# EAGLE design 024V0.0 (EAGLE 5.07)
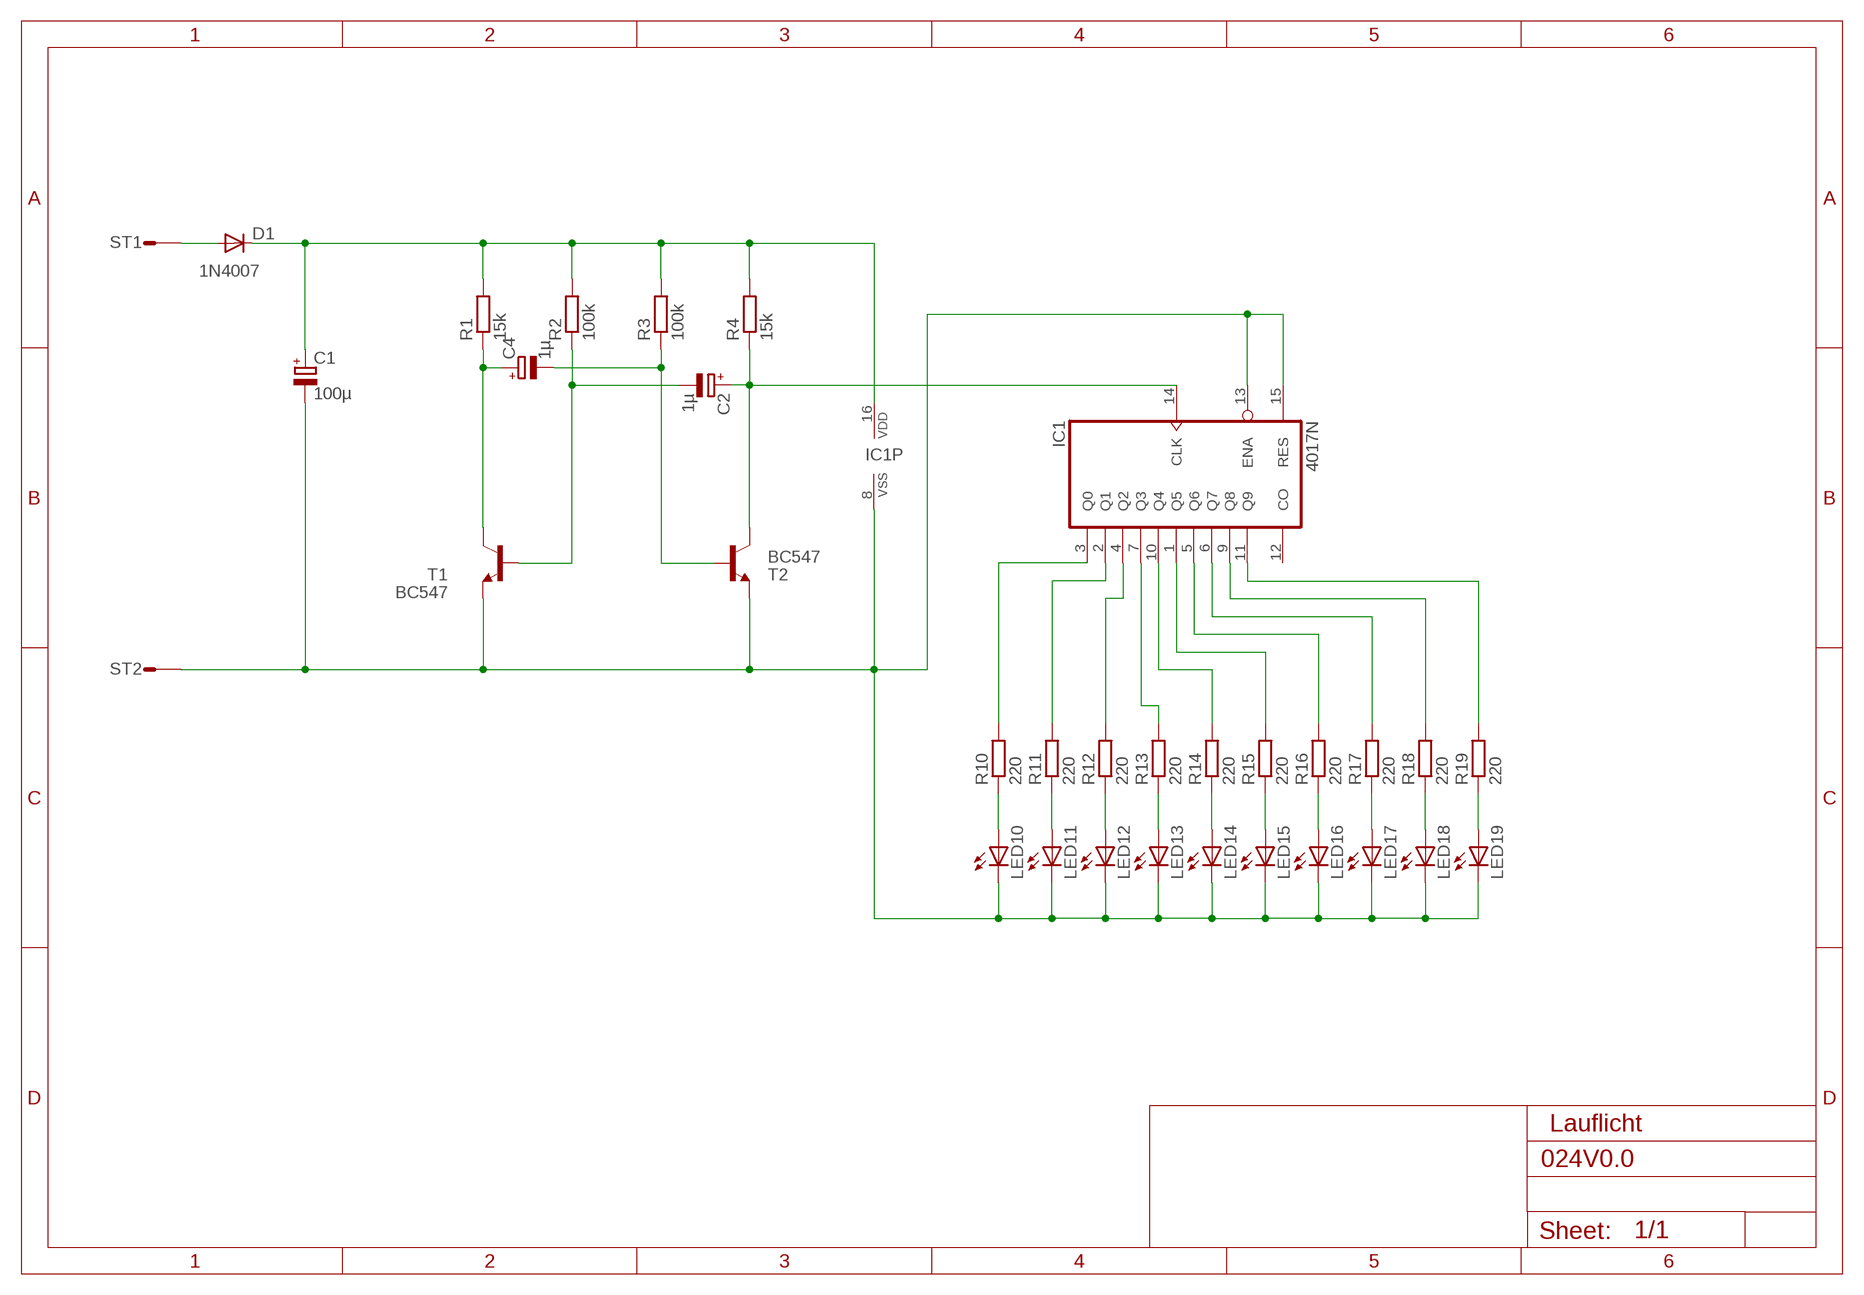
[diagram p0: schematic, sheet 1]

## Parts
C1  100µ  CPOL-EUE5-10.5  [E5-10,5]
C2  1µ  CPOL-EUE2.5-5  [E2,5-5]
C4  1µ  CPOL-EUE2.5-5  [E2,5-5]
D1  1N4007  1N4004  [DO41-10]
IC1  4017N  [DIL16]
LED10  LED3MM  [LED3MM]
LED11  LED3MM  [LED3MM]
LED12  LED3MM  [LED3MM]
LED13  LED3MM  [LED3MM]
LED14  LED3MM  [LED3MM]
LED15  LED3MM  [LED3MM]
LED16  LED3MM  [LED3MM]
LED17  LED3MM  [LED3MM]
LED18  LED3MM  [LED3MM]
LED19  LED3MM  [LED3MM]
R1  15k  R-EU_0207/10  [0207/10]
R2  100k  R-EU_0207/10  [0207/10]
R3  100k  R-EU_0207/10  [0207/10]
R4  15k  R-EU_0207/10  [0207/10]
R10  220  R-EU_0207/10  [0207/10]
R11  220  R-EU_0207/10  [0207/10]
R12  220  R-EU_0207/10  [0207/10]
R13  220  R-EU_0207/10  [0207/10]
R14  220  R-EU_0207/10  [0207/10]
R15  220  R-EU_0207/10  [0207/10]
R16  220  R-EU_0207/10  [0207/10]
R17  220  R-EU_0207/10  [0207/10]
R18  220  R-EU_0207/10  [0207/10]
R19  220  R-EU_0207/10  [0207/10]
ST1  ST2,8  [ST2,8]
ST2  ST2,8  [ST2,8]
T1  BC547  [TO92-5]
T2  BC547  [TO92-5]

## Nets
GND: C1.- IC1.8(VSS) IC1.13(ENA) IC1.15(RES) LED10.K(C) LED11.K(C) LED12.K(C) LED13.K(C) LED14.K(C) LED15.K(C) LED16.K(C) LED17.K(C) LED18.K(C) LED19.K(C) ST2.1(ST) T1.1(E) T2.1(E)
N$1: D1.A ST1.1(ST)
N$2: C1.+ D1.C IC1.16(VDD) R1.2 R2.2 R3.2 R4.2
N$4: C4.+ R1.1 T1.3(C)
N$5: C4.- R3.1 T2.2(B)
N$6: C2.+ IC1.14(CLK) R4.1 T2.3(C)
N$7: C2.- R2.1 T1.2(B)
N$8: LED10.A R10.1
N$9: LED11.A R11.1
N$10: LED12.A R12.1
N$11: LED13.A R13.1
N$12: LED14.A R14.1
N$13: LED15.A R15.1
N$14: LED16.A R16.1
N$15: LED17.A R17.1
N$16: LED18.A R18.1
N$17: LED19.A R19.1
N$18: IC1.3(Q0) R10.2
N$19: IC1.2(Q1) R11.2
N$20: IC1.4(Q2) R12.2
N$21: IC1.11(Q9) R19.2
N$22: IC1.9(Q8) R18.2
N$23: IC1.6(Q7) R17.2
N$24: IC1.5(Q6) R16.2
N$25: IC1.1(Q5) R15.2
N$26: IC1.10(Q4) R14.2
N$27: IC1.7(Q3) R13.2
Unconnected: IC1.12(CO)

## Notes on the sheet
- Lauflicht

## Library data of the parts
C1 = resistor:CPOL-EU: POLARIZED CAPACITOR, European symbol
C2 C4 = rcl:CPOL-EU: POLARIZED CAPACITOR, European symbol
D1 = diode:1N4004: DIODE
IC1 = 40xx:4017: COUNTER/DIVIDER
LED10-LED19 = led:LED: LED
R1-R4 R10-R19 = armin:R-EU_: RESISTOR, European symbol
ST1 ST2 = con-rib:ST2,8: RIBBON CABLE CONNECTOR
T1 T2 = armin:BC547: NPN TRANSISTOR

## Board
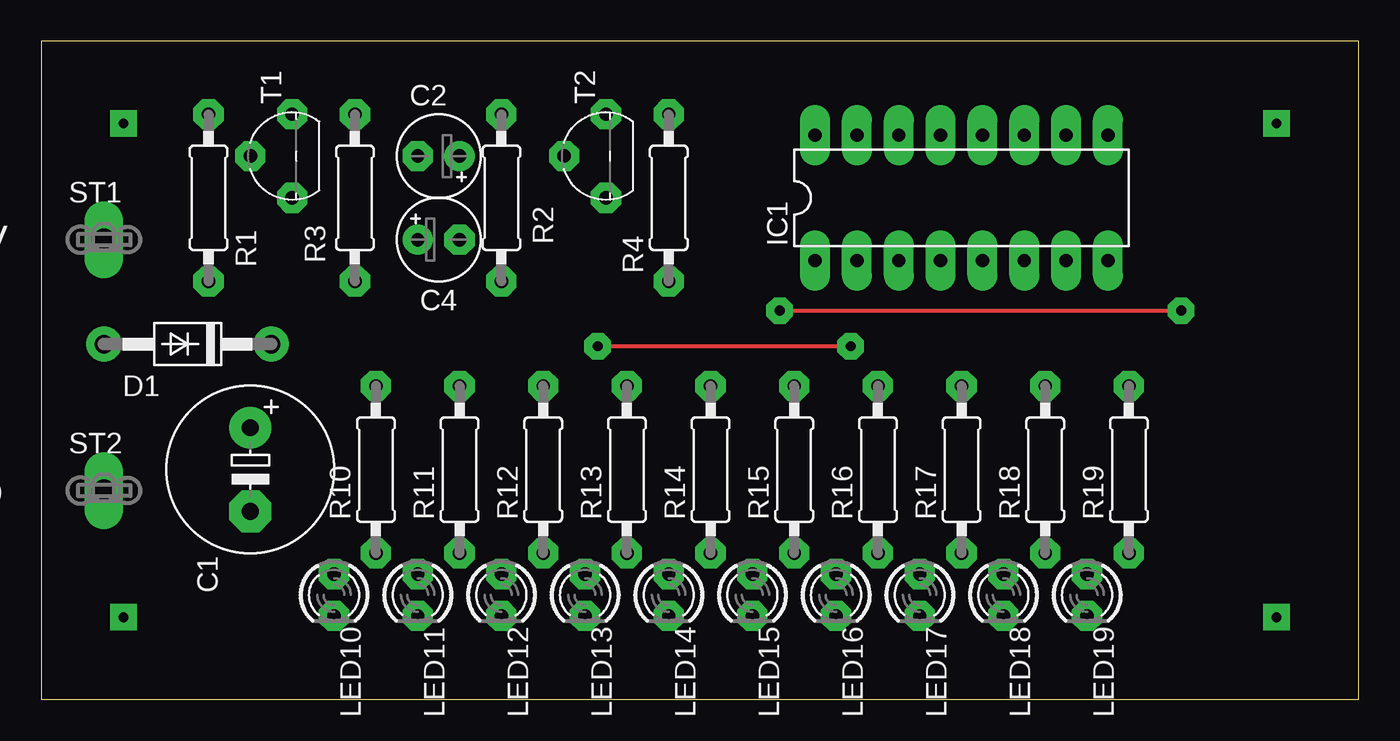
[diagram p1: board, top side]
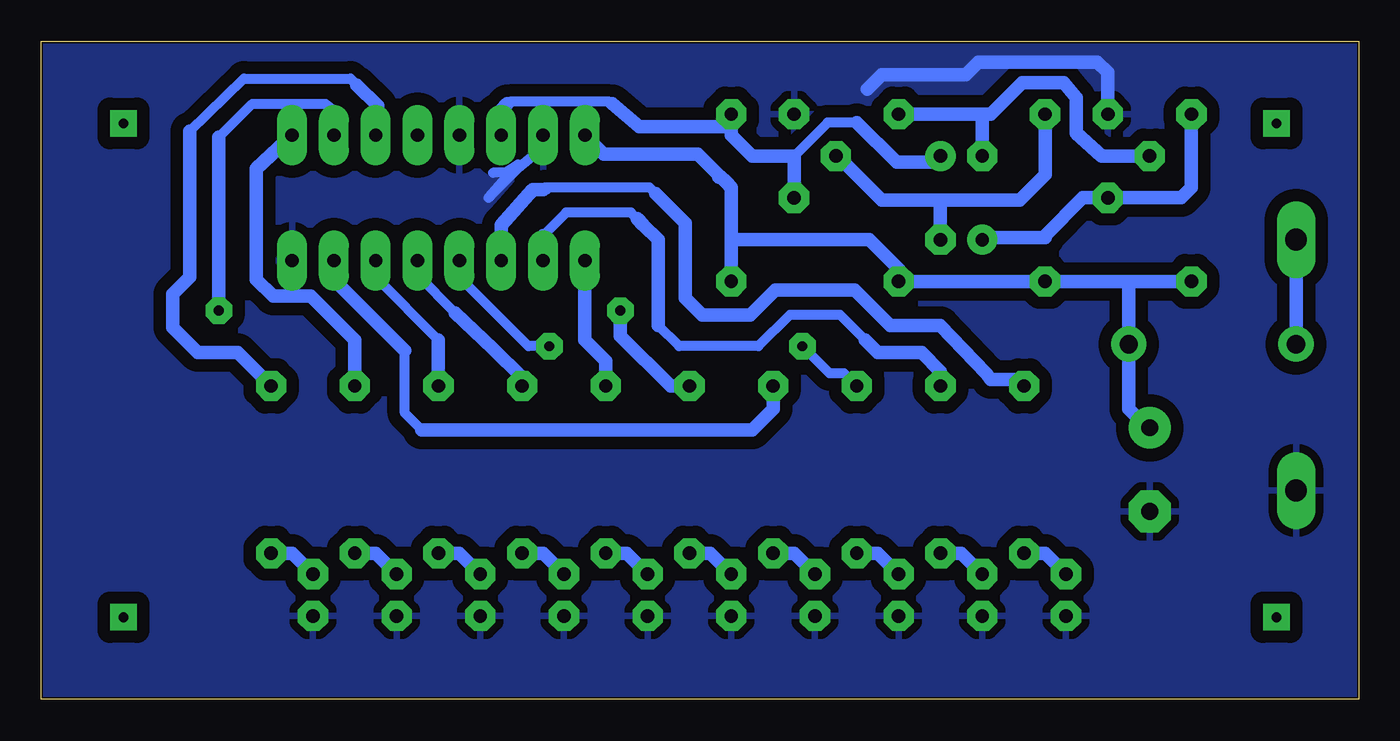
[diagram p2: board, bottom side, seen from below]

Size 80 x 40 mm. Coordinates in mm from the lower left corner, seen from the top.
Outline: 0,0 80,0 80,40 0,40 0,0
Copper layers (1*16): Top 0.035mm / dielectric 1.5mm / Bottom 0.035mm
Design rules "default *": minimum track width 10mil, minimum drill 24mil, track to track 30mil, track to pad 30mil, pad to pad 25mil, via to via 8mil, smd to smd 8mil, copper to edge 5mil, drill to drill 8mil, minimum pad ring 20mil, minimum via ring 20mil, stop-mask expansion 4mil, vias tented up to drill 0mil, thermal gap 20mil
bKeepout: 2 lines
bRestrict: 2 lines

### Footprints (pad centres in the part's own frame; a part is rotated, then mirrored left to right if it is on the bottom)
E5-10,5 = drill 1.016 pad 2.54 round: + -2.54,0 | drill 1.016 pad 2.54 octagon: - 2.54,0
E2,5-5 = drill 0.813 pad 1.6 round: + -1.27,0 | drill 0.813 pad 1.6 octagon: - 1.27,0
DO41-10 = drill 1.118 round: A 5.08,0; C -5.08,0
DIL16 = drill 0.813 long: 1 -8.89,-3.81; 2 -6.35,-3.81; 3 -3.81,-3.81; 4 -1.27,-3.81; 5 1.27,-3.81; 6 3.81,-3.81; 7 6.35,-3.81; 8 8.89,-3.81; 9 8.89,3.81; 10 6.35,3.81; 11 3.81,3.81; 12 1.27,3.81; 13 -1.27,3.81; 14 -3.81,3.81; 15 -6.35,3.81; 16 -8.89,3.81
LED3MM = drill 0.813 octagon: A -1.27,0; K 1.27,0
0207/10 = drill 0.813 octagon: 1 -5.08,0; 2 5.08,0
ST2,8 = drill 1.321 long: 1 0,0
TO92-5 = drill 0.813 octagon: 1 2.54,0; 2 0,2.54; 3 -2.54,0

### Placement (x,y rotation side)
C1  12.7,13.97 270 top
C2  24.13,33.02 180 top
C4  24.13,27.94 0 top
D1  8.89,21.59 180 top
IC1  55.88,30.48 0 top
LED10  17.78,6.35 270 top
LED11  22.86,6.35 270 top
LED12  27.94,6.35 270 top
LED13  33.02,6.35 270 top
LED14  38.1,6.35 270 top
LED15  43.18,6.35 270 top
LED16  48.26,6.35 270 top
LED17  53.34,6.35 270 top
LED18  58.42,6.35 270 top
LED19  63.5,6.35 270 top
R1  10.16,30.48 270 top
R2  27.94,30.48 270 top
R3  19.05,30.48 270 top
R4  38.1,30.48 270 top
R10  20.32,13.97 90 top
R11  25.4,13.97 90 top
R12  30.48,13.97 90 top
R13  35.56,13.97 90 top
R14  40.64,13.97 90 top
R15  45.72,13.97 90 top
R16  50.8,13.97 90 top
R17  55.88,13.97 90 top
R18  60.96,13.97 90 top
R19  66.04,13.97 90 top
ST1  3.81,27.94 0 top
ST2  3.81,12.7 0 top
T1  15.24,33.02 90 top
T2  34.29,33.02 90 top

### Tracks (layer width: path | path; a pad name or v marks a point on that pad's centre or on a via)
GND
  Bottom 0.61: IC1.15 49.53,33.53 51.05,32.26 52.83,30.48 51.05,32.51 51.82,32 52.58,32
  Bottom 0.813: T1.1 15.24,38.1 15.88,38.73 23.11,38.73 23.88,37.97 28.96,37.97 29.84,37.08
  pour Bottom: 0,0 0,40.64 80.01,40.64 80.01,0
  pour Bottom: 60.07,12.45 72.01,12.45 72.01,15.88 60.07,15.88
  pour Bottom: 1.52,7.87 7.11,7.87 7.11,10.41 1.52,10.41
  pour Bottom: 7.87,21.34 7.87,31.37 5.84,31.37 5.84,21.34
N$1
  Bottom 0.813: D1.A ST1.1
N$2
  Bottom 0.813: C1.+ 12.83,16.51 13.97,17.65 D1.C 13.97,25.27 14.1,25.4 | 38.8,31.81 38.42,31.43 38.1,31.11 38.1,28.07 | 38.1,28.07 R4.2 | 38.1,28.07 37.97,27.94 29.72,27.94 27.94,26.16 R2.2 R3.2 14.1,25.4 | 38.8,31.81 38.86,31.75 | IC1.16 45.85,33.15 40.13,33.15 38.8,31.81 | 14.1,25.4 R1.2
N$4
  Bottom 0.813: C4.+ 22.73,28.07 19.05,28.07 19.05,28.19 16.76,30.48 T1.3 10.79,30.48 10.16,31.11 R1.1
N$5
  Bottom 0.813: 25.4,28.32 C4.- 25.4,30.35 | R3.1 19.05,31.88 20.57,30.35 25.4,30.35 | T2.2 31.62,33.02 28.96,30.35 25.4,30.35
N$6
  Bottom 0.61: 30.48,35.05 32.26,35.05 34.29,33.02 | 45.34,36.2 45.47,36.2 45.47,36.32 51.56,36.32 51.56,36.2 51.69,36.2
  Bottom 0.813: C2.+ 25.78,32.64 28.07,32.64 30.48,35.05 | 34.29,33.02 34.29,32.89 | 34.29,32.89 T2.3 | 38.1,34.8 38.1,34.29 36.83,33.02 34.42,33.02 34.29,32.89 | IC1.14 52.07,35.81 51.69,36.2 | 45.34,36.2 43.69,34.8 38.1,34.8 | 38.1,34.8 R4.1
N$7
  Bottom 0.813: T1.2 15.62,33.02 17.14,34.42 17.14,36.58 17.91,37.47 20.45,37.47 22.35,35.56 22.86,35.56 | 22.86,35.56 C2.- | 22.86,35.56 R2.1
N$8
  Bottom 0.813: R10.1 19.05,8.89 LED10.A
N$9
  Bottom 0.813: R11.1 24.13,8.89 LED11.A
N$10
  Bottom 0.813: R12.1 29.21,8.89 LED12.A
N$11
  Bottom 0.813: R13.1 34.29,8.89 LED13.A
N$12
  Bottom 0.813: R14.1 39.37,8.89 LED14.A
N$13
  Bottom 0.813: R15.1 44.45,8.89 LED15.A
N$14
  Bottom 0.813: R16.1 49.53,8.89 LED16.A
N$15
  Bottom 0.813: R17.1 54.61,8.89 LED17.A
N$16
  Bottom 0.813: R18.1 59.69,8.89 LED18.A
N$17
  Bottom 0.813: LED19.A 64.77,8.89 R19.1
N$18
  Bottom 0.61: 49.53,30.99 49.28,30.99 49.4,31.11 43.05,31.11 42.67,30.73
  Bottom 0.813: R10.2 20.32,19.43 22.35,19.43 22.61,19.81 25.4,22.73 28.45,22.73 30.61,24.89 35.43,24.89 36.96,23.37 39.88,23.37 40.89,24.38 40.89,28.96 42.67,30.73 | IC1.3 52.07,28.83 50.16,30.99 49.53,30.99
N$19
  Bottom 0.61: 29.97,21.84 31.5,23.37 34.54,23.37 36.45,21.46 41.27,21.46 42.55,22.73 | 49.53,28.19 48.13,29.59 44.2,29.59 43.43,28.83
  Bottom 0.813: R11.2 25.4,19.94 26.54,21.08 29.21,21.08 29.97,21.84 | 49.53,28.19 IC1.2 | 43.81,29.21 43.43,28.83 42.55,27.94 42.55,22.73
N$20  (via drill 0.6)
  Top 0.254: v33.78,21.46 v49.15,21.46
  Bottom 0.61: IC1.4 54.61,25.65 50.42,21.46 v49.15,21.46 | v33.78,21.46 32.13,19.81 31.24,19.81 R12.2
N$21
  Bottom 0.61: 60.83,37.34 61.21,37.72 67.69,37.72 70.99,34.54
  Bottom 0.813: 66.55,19.05 R19.2 68.07,21.08 70.48,21.08 72.01,22.61 72.01,24.64 70.99,25.65 70.99,34.54 | 60.83,37.34 59.56,36.07 59.56,34.42 IC1.11
N$22
  Bottom 0.813: IC1.9 66.93,32.26 66.93,25.53 65.91,24.51 63.63,24.51 60.96,21.84 R18.2
N$23
  Bottom 0.61: 55.88,21.84 59.69,25.65
  Bottom 0.813: 59.69,25.65 IC1.6 | R17.2 55.88,21.84
N$24
  Bottom 0.61: 54.86,23.5 57.15,25.78
  Bottom 0.813: 57.15,25.78 IC1.5 | 54.86,23.5 52.58,21.34 50.8,19.56 R16.2
N$25
  Bottom 0.813: IC1.1 46.99,21.84 45.72,20.57 R15.2
N$26  (via drill 0.6)
  Top 0.254: v44.83,23.62 v69.22,23.62
  Bottom 0.61: 69.22,34.16 67.18,36.2 62.74,36.2 62.23,35.81 IC1.10
  Bottom 0.813: R14.2 41.78,19.05 44.83,22.1 v44.83,23.62 | v69.22,23.62 69.22,34.16
N$27
  Bottom 0.61: 57.91,21.21 57.91,17.4 56.9,16.38
  Bottom 0.813: IC1.7 62.23,25.53 57.91,21.21 | 56.9,16.38 36.83,16.38 35.56,17.65 R13.2
N$28  (via drill 0.6)
  other vias: 5,35
N$29  (via drill 0.6)
  other vias: 75,35
N$30  (via drill 0.6)
  other vias: 75,5
N$31  (via drill 0.6)
  other vias: 5,5

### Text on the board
tPlace: +5 .. 12V | GND
bRestrict: +5 .. 12V | 024V0.0 | GND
